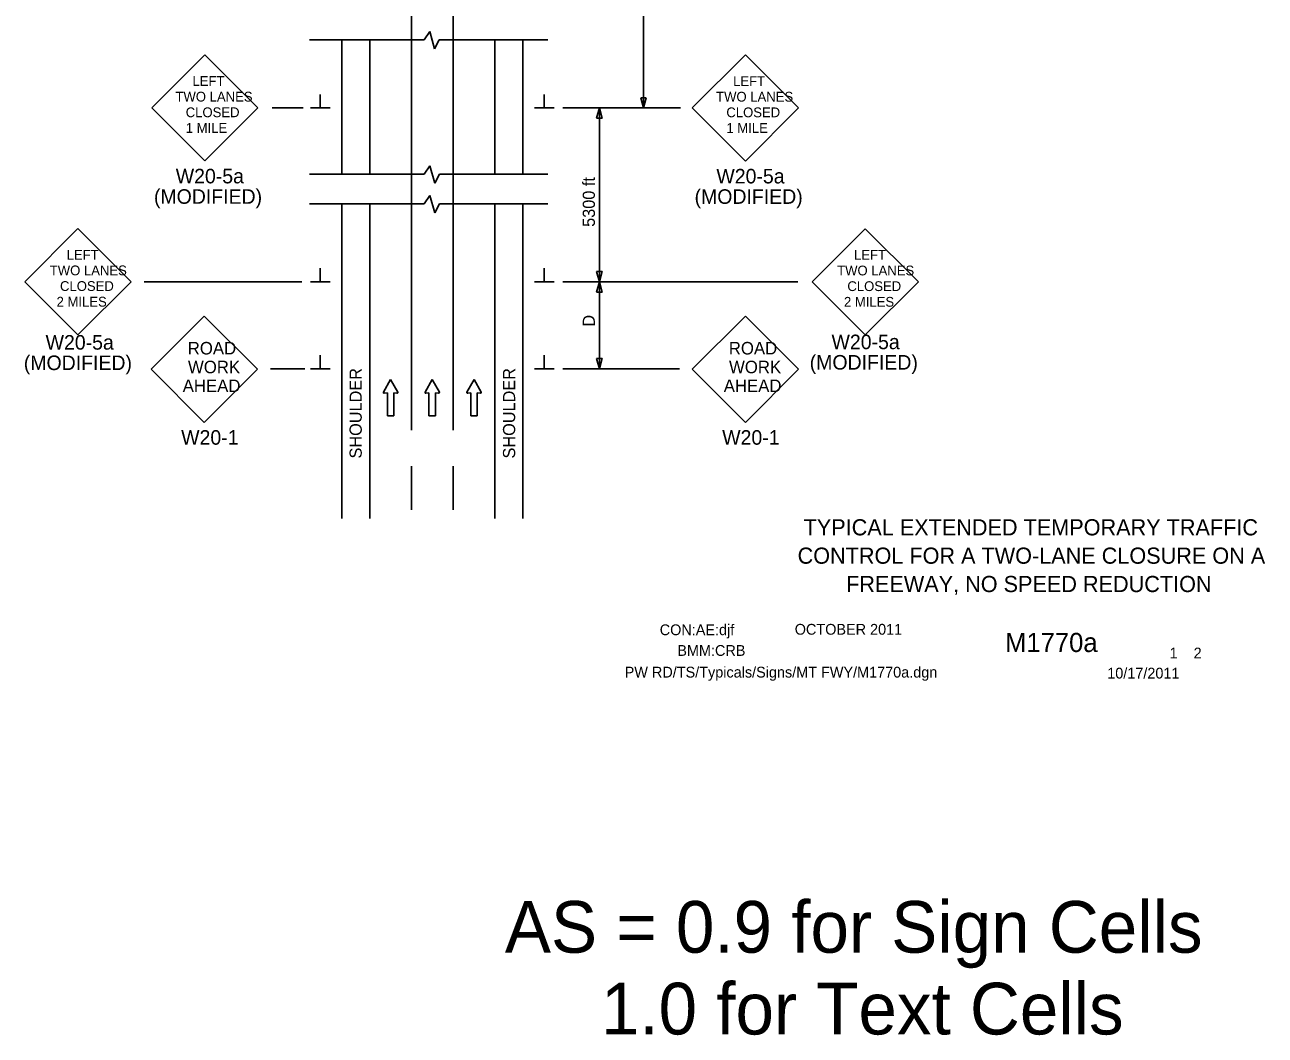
# Model space of a CAD drawing. Extents: x 16726 to 18475, y 7014 to 8214.
# Drawn here: x 16726 to 17439, y 7014 to 7595 of the extents above; entities that cross this region are included whole.
import ezdxf

# ---------------------------------------------------------------- set-up
doc = ezdxf.new("R2010")
doc.units = 0
for name, color, linetype in [('ALI_LEGAL_EX', 7, 'Continuous'), ('BORDER', 7, 'Continuous'), ('BORDER_SIGNAL_WO', 7, 'Continuous'), ('MT_SCRATCH_LEVEL_E', 7, 'Continuous'), ('PAVT_EDGE_EX', 7, 'Continuous'), ('TRAFFIC_SIGNS_PR', 7, 'Continuous'), ('TYPICAL_TEXT_DIMEN_PR', 7, 'Continuous')]:
    doc.layers.add(name, color=color, linetype=linetype)

msp = doc.modelspace()

# ---------------------------------------------------------------- linework, layer by layer
at = {"layer": 'ALI_LEGAL_EX'}
for p, q in [((16947.99, 8191.42), (16947.99, 7362.23)), ((16971.99, 8191.42), (16971.99, 7362.23)), ((16971.99, 8191.42), (16971.99, 7362.23))]:
    msp.add_line(p, q, dxfattribs=at)
for points in [[(16947.99, 7541.42), (16947.99, 7516.42)], [(16971.99, 7541.42), (16971.99, 7516.42)], [(16947.99, 7441.42), (16947.99, 7416.42)], [(16971.99, 7441.42), (16971.99, 7416.42)], [(16947.99, 7341.42), (16947.99, 7316.42)], [(16971.99, 7316.42), (16971.99, 7341.42)], [(16971.99, 7341.42), (16971.99, 7316.42)]]:
    msp.add_lwpolyline(points, dxfattribs=at)
at = {"layer": 'MT_SCRATCH_LEVEL_E'}
for p, q in [((16935.99, 7391.36), (16931.88, 7384.12)), ((16940.13, 7384.12), (16935.99, 7391.36)), ((16959.89, 7391.36), (16955.78, 7384.12)), ((16964.04, 7384.12), (16959.89, 7391.36)), ((16983.94, 7391.36), (16979.83, 7384.12)), ((16988.09, 7384.12), (16983.94, 7391.36)), ((16932.36, 7383.43), (16934.13, 7383.75)), ((16934.13, 7383.75), (16934.13, 7370.49)), ((16937.88, 7370.49), (16937.88, 7383.75)), ((16937.88, 7383.75), (16939.65, 7383.43)), ((16956.26, 7383.43), (16958.04, 7383.75)), ((16958.04, 7383.75), (16958.04, 7370.49)), ((16961.78, 7370.49), (16961.78, 7383.75)), ((16961.78, 7383.75), (16963.56, 7383.43)), ((16980.31, 7383.43), (16982.09, 7383.75)), ((16982.09, 7383.75), (16982.09, 7370.49)), ((16985.83, 7370.49), (16985.83, 7383.75)), ((16985.83, 7383.75), (16987.61, 7383.43)), ((16934.13, 7370.49), (16937.88, 7370.49)), ((16958.04, 7370.49), (16961.78, 7370.49)), ((16982.09, 7370.49), (16985.83, 7370.49))]:
    msp.add_line(p, q, dxfattribs=at)
for centre, start, end in [((16932.28, 7383.89), 150.42484, 279.96381), ((16939.72, 7383.89), 260.03619, 29.77312), ((16956.19, 7383.89), 150.42484, 279.96381), ((16963.63, 7383.89), 260.03619, 29.77312), ((16980.24, 7383.89), 150.42484, 279.96381), ((16987.68, 7383.89), 260.03619, 29.77312)]:
    msp.add_arc(centre, 0.463, start, end, dxfattribs=at)
at = {"layer": 'PAVT_EDGE_EX'}
for p, q in [((16907.99, 7586.58), (16907.99, 7509.44)), ((16923.99, 7586.58), (16923.99, 7509.44)), ((16995.99, 7586.6), (16995.99, 7509.44)), ((17011.99, 7586.6), (17011.99, 7509.44)), ((16907.99, 7492.3), (16907.99, 7311.48)), ((16923.99, 7492.3), (16923.99, 7311.48)), ((16995.99, 7492.3), (16995.99, 7311.48)), ((17011.99, 7492.3), (17011.99, 7311.48))]:
    msp.add_line(p, q, dxfattribs=at)
at = {"layer": 'TRAFFIC_SIGNS_PR'}
for p, q in [((16829.23, 7578.07), (16798.68, 7547.52)), ((16859.78, 7547.52), (16829.23, 7578.07)), ((17139.98, 7578.03), (17109.43, 7547.49)), ((17170.53, 7547.49), (17139.98, 7578.03)), ((16798.68, 7547.52), (16829.23, 7516.98)), ((16829.23, 7516.98), (16859.78, 7547.52)), ((17109.43, 7547.49), (17139.98, 7516.94)), ((17139.98, 7516.94), (17170.53, 7547.49)), ((16756.29, 7478.1), (16725.74, 7447.55)), ((16786.84, 7447.55), (16756.29, 7478.1)), ((17208.86, 7478.03), (17178.32, 7447.49)), ((17239.41, 7447.49), (17208.86, 7478.03)), ((16725.74, 7447.55), (16756.29, 7417.01)), ((16756.29, 7417.01), (16786.84, 7447.55)), ((17178.32, 7447.49), (17208.86, 7416.94)), ((17208.86, 7416.94), (17239.41, 7447.49)), ((16828.93, 7427.8), (16798.38, 7397.25)), ((16859.47, 7397.25), (16828.93, 7427.8)), ((17139.91, 7427.8), (17109.37, 7397.25)), ((17170.46, 7397.25), (17139.91, 7427.8)), ((16798.38, 7397.25), (16828.93, 7366.7)), ((16828.93, 7366.7), (16859.47, 7397.25)), ((17109.37, 7397.25), (17139.91, 7366.7)), ((17139.91, 7366.7), (17170.46, 7397.25))]:
    msp.add_line(p, q, dxfattribs=at)
at = {"layer": 'TYPICAL_TEXT_DIMEN_PR'}
for p, q in [((17081.42, 7847.49), (17081.42, 7547.49)), ((16955.24, 7586.58), (16889.3, 7586.58)), ((16958.5, 7591.38), (16955.24, 7586.58)), ((16961.24, 7581.44), (16958.5, 7591.38)), ((16963.98, 7586.58), (16961.24, 7581.44)), ((17026.32, 7586.58), (16963.98, 7586.58)), ((16895.61, 7547.49), (16895.61, 7555.27)), ((17024.36, 7547.49), (17024.36, 7555.27)), ((17081.42, 7547.49), (17079.85, 7553.35)), ((17079.85, 7553.35), (17081.42, 7553.35)), ((17081.42, 7553.35), (17082.99, 7553.35)), ((17082.99, 7553.35), (17081.42, 7547.49)), ((16867.98, 7547.49), (16885.78, 7547.49)), ((16889.99, 7547.49), (16901.24, 7547.49)), ((17029.99, 7547.49), (17018.74, 7547.49)), ((17102.61, 7547.49), (17034.99, 7547.49)), ((17054.42, 7541.63), (17055.99, 7547.49)), ((17055.99, 7547.49), (17055.99, 7447.49)), ((17055.99, 7547.49), (17057.56, 7541.63)), ((17055.99, 7541.63), (17054.42, 7541.63)), ((17057.56, 7541.63), (17055.99, 7541.63)), ((16955.33, 7509.43), (16889.39, 7509.43)), ((16958.59, 7514.23), (16955.33, 7509.43)), ((16961.33, 7504.29), (16958.59, 7514.23)), ((16964.07, 7509.43), (16961.33, 7504.29)), ((17026.41, 7509.43), (16964.07, 7509.43)), ((16958.59, 7497.09), (16955.33, 7492.29)), ((16961.33, 7487.15), (16958.59, 7497.09)), ((16955.33, 7492.29), (16889.39, 7492.29)), ((16964.07, 7492.29), (16961.33, 7487.15)), ((17026.41, 7492.29), (16964.07, 7492.29)), ((16895.61, 7447.49), (16895.61, 7455.27)), ((17024.36, 7447.49), (17024.36, 7455.27)), ((17055.99, 7447.49), (17054.42, 7453.35)), ((17054.42, 7453.35), (17055.99, 7453.35)), ((17055.99, 7453.35), (17057.56, 7453.35)), ((17057.56, 7453.35), (17055.99, 7447.49)), ((16794.37, 7447.49), (16884.99, 7447.49)), ((16889.99, 7447.49), (16901.24, 7447.49)), ((17029.99, 7447.49), (17018.74, 7447.49)), ((17170.11, 7447.49), (17034.99, 7447.49)), ((17054.42, 7441.63), (17055.99, 7447.49)), ((17055.99, 7447.49), (17055.99, 7397.49)), ((17055.99, 7447.49), (17057.56, 7441.63)), ((17055.99, 7441.63), (17054.42, 7441.63)), ((17057.56, 7441.63), (17055.99, 7441.63)), ((16895.61, 7397.49), (16895.61, 7405.27)), ((17024.36, 7397.49), (17024.36, 7405.27)), ((17055.99, 7397.49), (17054.42, 7403.35)), ((17054.42, 7403.35), (17055.99, 7403.35)), ((17055.99, 7403.35), (17057.56, 7403.35)), ((17057.56, 7403.35), (17055.99, 7397.49)), ((16866.88, 7397.49), (16886.74, 7397.49)), ((16889.99, 7397.49), (16901.24, 7397.49)), ((17029.99, 7397.49), (17018.74, 7397.49)), ((17101.98, 7397.49), (17034.99, 7397.49))]:
    msp.add_line(p, q, dxfattribs=at)

# ---------------------------------------------------------------- texts
at = {"layer": 'BORDER'}
for s, p in [('TYPICAL EXTENDED TEMPORARY TRAFFIC', (17173.38, 7301.69)), ('CONTROL FOR A TWO-LANE CLOSURE ON A', (17169.94, 7285.39)), ('FREEWAY, NO SPEED REDUCTION', (17197.83, 7269.09))]:
    msp.add_text(s, height=9.3, dxfattribs=at).set_placement(p)
at = {"layer": 'BORDER_SIGNAL_WO'}
for s, height, p in [('    OCTOBER 2011', 6.2, (17159.08, 7244.59)), ('CON:AE:djf  ', 6.2, (17090.69, 7244.31)), ('    M1770a   ', 11, (17272.86, 7234.63)), ('BMM:CRB', 6.2, (17100.81, 7232.42)), (' 1    2 ', 6.2, (17381.45, 7230.95)), ('PW RD/TS/Typicals/Signs/MT FWY/M1770a.dgn      ', 6.2, (17070.55, 7219.96)), ('10/17/2011', 6.2, (17347.93, 7219.38)), ('AS = 0.9 for Sign Cells', 29.7271, (17001.67, 7061.73)), ('     1.0 for Text Cells', 29.7271, (17001.67, 7014.72))]:
    msp.add_text(s, height=height, dxfattribs=at).set_placement(p)
at = {"layer": 'TRAFFIC_SIGNS_PR'}
for s, height, p in [('LEFT', 5.625, (16822.12, 7560.16)), ('LEFT', 5.625, (17132.87, 7560.12)), ('TWO LANES', 5.625, (16812.35, 7551.16)), ('TWO LANES', 5.625, (17123.1, 7551.12)), ('CLOSED', 5.625, (16818.24, 7542.16)), ('CLOSED', 5.625, (17128.99, 7542.13)), ('1 MILE', 5.625, (16818.26, 7533.16)), ('1 MILE', 5.625, (17129.01, 7533.13)), ('W20-5a', 8.37, (16812.51, 7504.11)), ('W20-5a', 8.37, (17123.26, 7504.07)), ('(MODIFIED)', 8.37, (16799.97, 7492.36)), ('(MODIFIED)', 8.37, (17110.72, 7492.33)), ('LEFT', 5.625, (16749.82, 7460.25)), ('LEFT', 5.625, (17202.39, 7460.19)), ('TWO LANES', 5.625, (16740.1, 7451.25)), ('TWO LANES', 5.625, (17192.67, 7451.19)), ('CLOSED', 5.625, (16745.98, 7442.25)), ('CLOSED', 5.625, (17198.55, 7442.19)), ('2 MILES', 5.625, (16744.01, 7433.25)), ('2 MILES', 5.625, (17196.58, 7433.19)), ('W20-5a', 8.37, (16737.7, 7408.5)), ('W20-5a', 8.37, (17189.44, 7408.77)), ('ROAD', 7.2, (16819.41, 7405.73)), ('ROAD', 7.2, (17130.4, 7405.73)), ('(MODIFIED)', 8.37, (16725.17, 7396.75)), ('WORK', 7.2, (16819.53, 7394.93)), ('WORK', 7.2, (17130.52, 7394.93)), ('(MODIFIED)', 8.37, (17176.9, 7397.03)), ('AHEAD', 7.2, (16816.51, 7384.13)), ('AHEAD', 7.2, (17127.49, 7384.13)), ('W20-1', 8.37, (16815.62, 7353.83)), ('W20-1', 8.37, (17126.6, 7353.83))]:
    msp.add_text(s, height=height, dxfattribs=at).set_placement(p)
at = {"layer": 'TYPICAL_TEXT_DIMEN_PR'}
for s, p in [('5300 ft', (17053.43, 7479.09)), ('D', (17053.43, 7421.71)), ('SHOULDER', (16919.41, 7345.9)), ('SHOULDER', (17007.6, 7345.9))]:
    msp.add_text(s, height=7, rotation=90, dxfattribs=at).set_placement(p)

doc.saveas('drawing.dxf')
